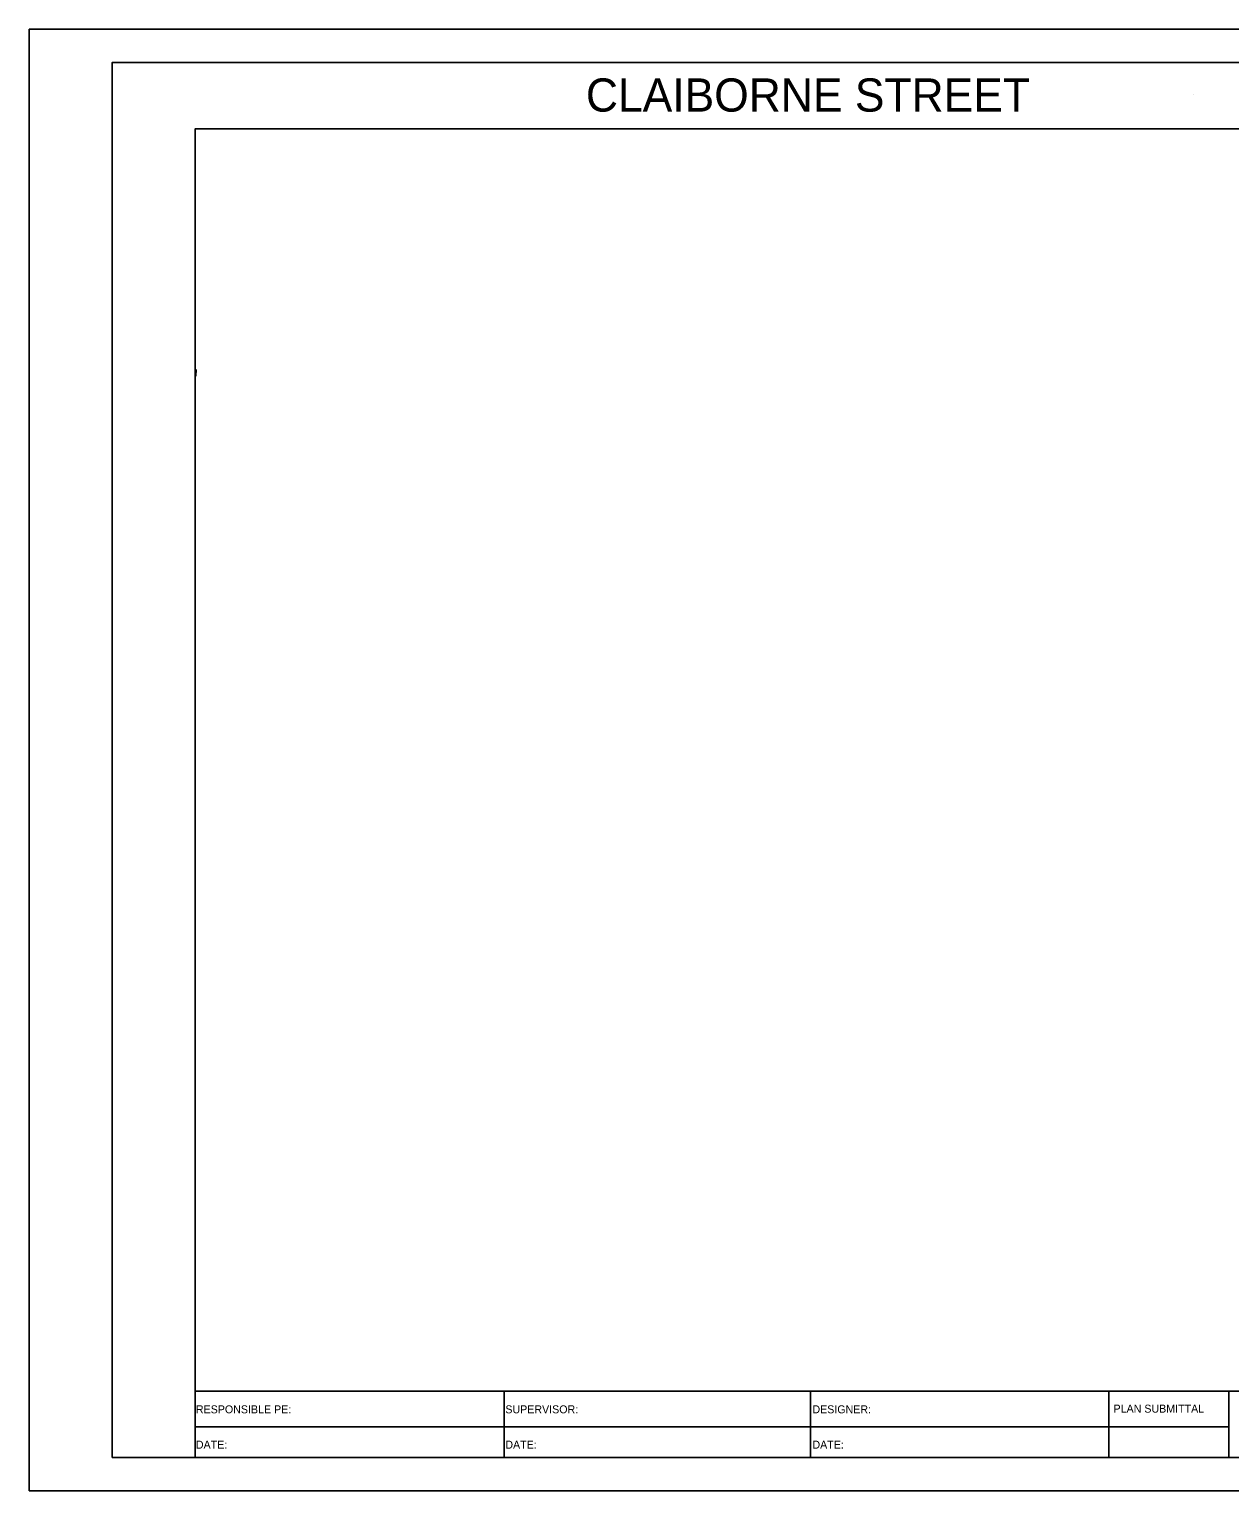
# Model space of a CAD drawing. Extents: x 1797478 to 1802796, y 246529 to 250952.
# Drawn here: x 1802116 to 1802296.8, y 250064.4 to 250284.4 of the extents above; entities that cross this region are included whole.
import ezdxf

# ---------------------------------------------------------------- set-up
doc = ezdxf.new("R2010")
doc.units = 0
for name, color, linetype in [('2', 7, 'Continuous'), ('ANNO-SHT', 7, 'Continuous'), ('ANNO-TXT', 7, 'Continuous'), ('AXIS', 7, 'Continuous'), ('DRAINAGE', 7, 'Continuous'), ('Level 1', 7, 'Continuous'), ('Level 62', 7, 'Continuous'), ('SHT-BDR', 7, 'Continuous'), ('SHT-BNDRY', 7, 'Continuous')]:
    doc.layers.add(name, color=color, linetype=linetype)

# ---------------------------------------------------------------- blocks, each defined once
blk = doc.blocks.new('SC47208')
at = {"layer": 'Level 1'}
blk.add_line((0, 0), (0, 0), dxfattribs=at)

msp = doc.modelspace()

# ---------------------------------------------------------------- linework, layer by layer
at = {"layer": '2'}
msp.add_lwpolyline([(1802141.12, 250233.21), (1802141.1, 250232.21)], dxfattribs=at)
msp.add_lwpolyline([(1802141.12, 250233.21), (1802141.1, 250232.21)], dxfattribs=at)
at = {"layer": 'AXIS'}
msp.add_line((1802141, 250189.42), (1802141, 250189.43), dxfattribs=at)
at = {"layer": 'Level 62'}
msp.add_lwpolyline([(1802116, 250064.42), (1802456, 250064.42), (1802456, 250284.42), (1802116, 250284.42)], close=True, dxfattribs=at)
at = {"layer": 'SHT-BDR'}
msp.add_lwpolyline([(1802141, 250079.43), (1802441, 250079.43), (1802441, 250269.43), (1802141, 250269.43)], close=True, dxfattribs=at)
at = {"layer": 'SHT-BNDRY'}
for p, q in [((1802141, 250069.42), (1802141, 250079.43)), ((1802187.52, 250079.43), (1802187.52, 250069.42)), ((1802233.67, 250069.42), (1802233.67, 250079.43)), ((1802278.59, 250069.42), (1802278.59, 250079.43)), ((1802296.63, 250069.42), (1802296.63, 250079.43)), ((1802141, 250074.03), (1802296.63, 250074.03))]:
    msp.add_line(p, q, dxfattribs=at)
msp.add_lwpolyline([(1802128.5, 250069.42), (1802451, 250069.42), (1802451, 250279.42), (1802128.5, 250279.42)], close=True, dxfattribs=at)

# ---------------------------------------------------------------- block references
at = {"layer": 'DRAINAGE', "xscale": 0.2, "yscale": 0.20000000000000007, "rotation": -116.41666666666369}
msp.add_blockref('SC47208', (1802291.32, 250274.62), dxfattribs=at)
msp.add_blockref('SC47208', (1802291.32, 250274.62), dxfattribs=at)

# ---------------------------------------------------------------- texts
at = {"layer": 'ANNO-SHT'}
msp.add_text('            CLAIBORNE STREET            ', height=4.9995, rotation=360, dxfattribs=at).set_placement((1802177.54, 250272.02))
at = {"layer": 'ANNO-TXT'}
for s, p in [('RESPONSIBLE PE:', (1802141.1, 250076.08)), ('SUPERVISOR:', (1802187.7, 250076.08)), ('DESIGNER:', (1802233.94, 250076.08)), ('PLAN SUBMITTAL', (1802279.28, 250076.18)), ('DATE:', (1802141.1, 250070.76)), ('DATE:', (1802187.7, 250070.76)), ('DATE:', (1802233.94, 250070.76))]:
    msp.add_text(s, height=1.2, rotation=360, dxfattribs=at).set_placement(p)

doc.saveas('drawing.dxf')
